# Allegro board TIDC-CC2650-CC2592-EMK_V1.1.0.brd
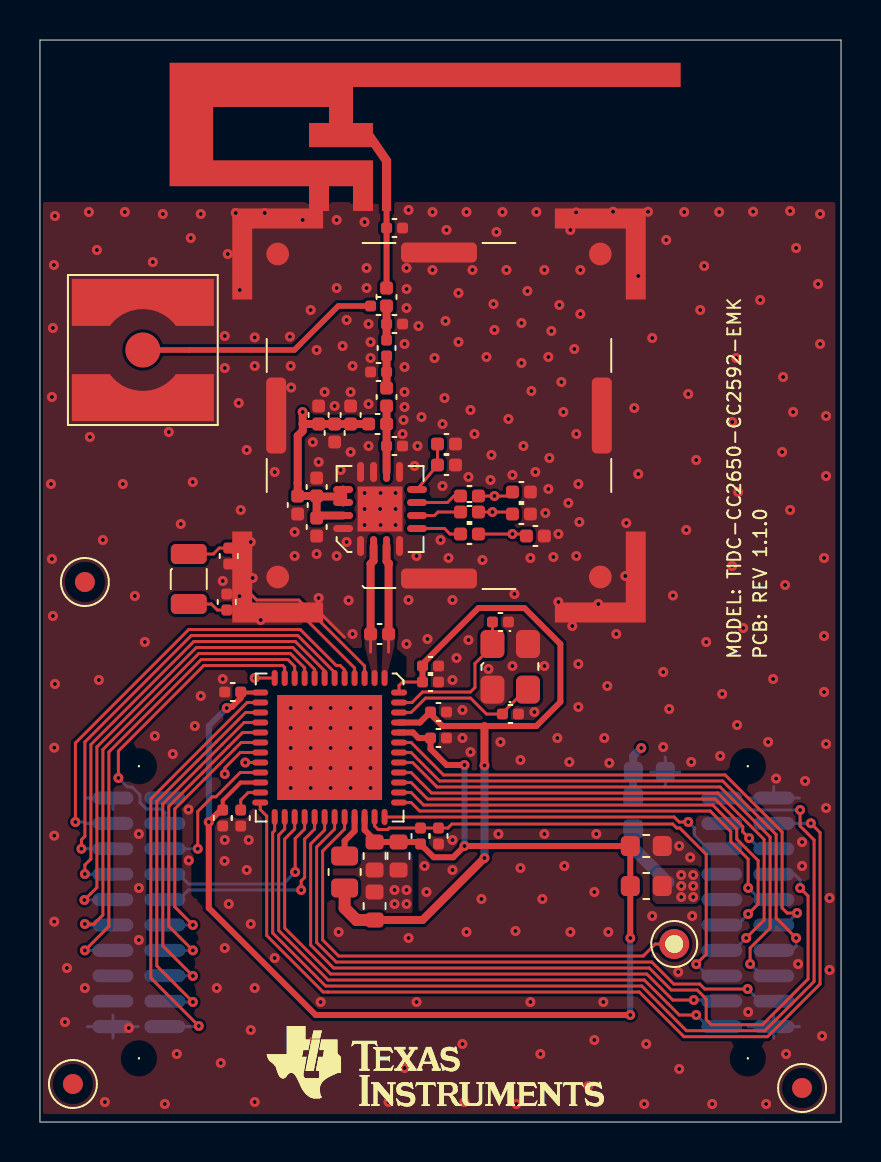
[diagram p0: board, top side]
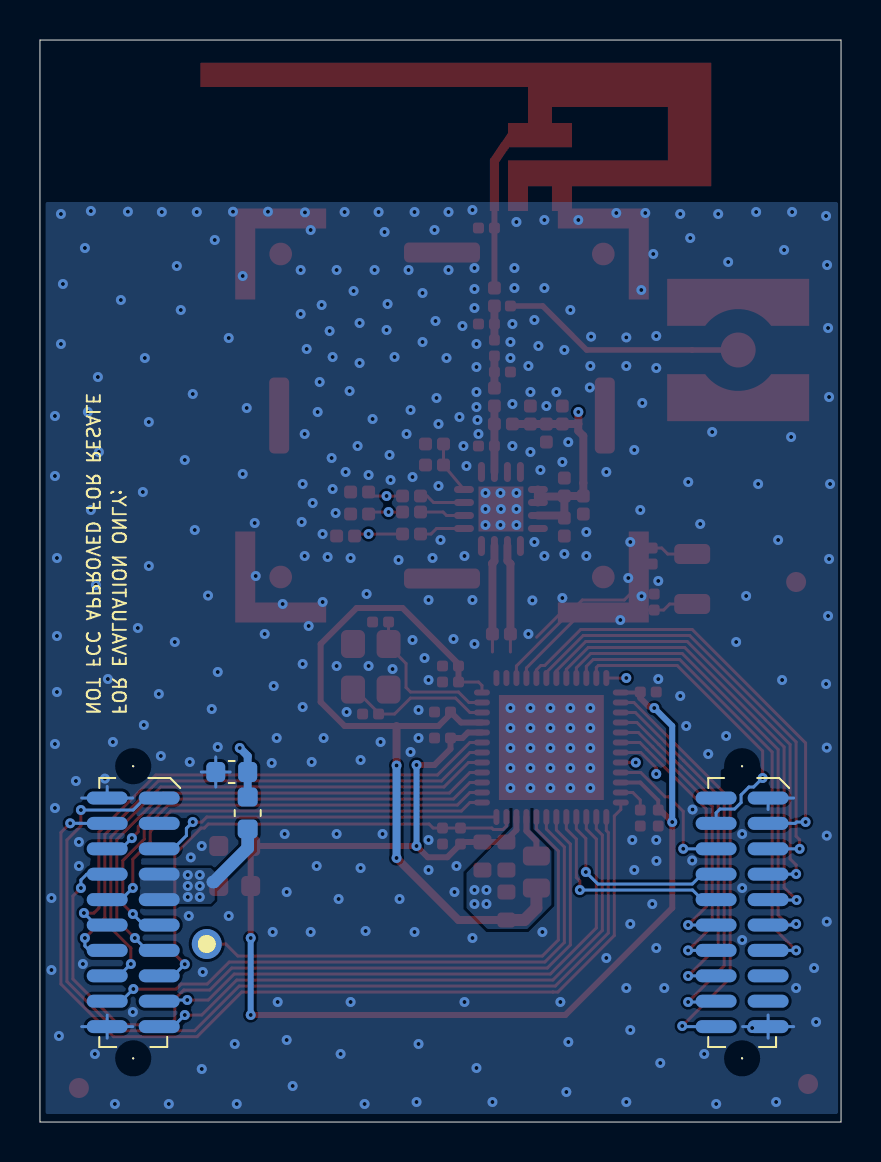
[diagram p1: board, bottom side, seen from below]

Outline 40.1 x 54.1 mm; copper layers: TOP, L2, L3, BOTTOM. Coordinates in mm from the lower left corner of the outline.
Outline path: 0,54.1 0,0 40.1,0 40.1,54.1 0,54.1

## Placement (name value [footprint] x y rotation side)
A1  2.4GHz  [ANTENNA_DN007N]  17.35 45.8 0 top
C1  10uF  [CAPC1608X90N]  16.75 10.1 90 top
C2  DNM  [CAPC1608X90N#2]  29.55 13.8 0 top
C3  100nF  [CAPC1005X60N#2]  10.05 21.5 180 top
C4  100nF  [CAPC1005X60N#2]  9.15 15.6 270 top
C5  100nF  [CAPC1005X60N#2]  19.55 19.2 0 top
C6  10uF  [CAPC1608X90N]  16.75 14 270 top
C7  100nF  [CAPC1608X90N]  17.95 14 270 top
C8  100nF  [CAPC1005X60N#2]  19.15 22 0 top
C9  100nF  [CAPC1005X60N#2]  19.55 20.5 0 top
C10  DNM_0402  [CAPC1005X60N#2]  19.15 22.8 0 top
C11  2.2uF  [CAPC1608X90N#2]  29.7 17.5 0 bottom
C12  2.2pF  [CAPC1005X60N#2]  17.35 33.8 0 top
C13  2.2pF  [CAPC1005X60N#2]  17.35 37.5 180 top
C14  1pF  [CAPC1005X60N#2]  17.35 39.9 0 top
C15  DNM_0402  [CAPC1005X60N#2]  17.35 44.7 0 top
C16  1nF  [CAPC1005X60N]  13.85 31.3 90 top
C17  12pF  [CAPC1005X60N#2]  9.45 28.7 270 top
C18  12pF  [CAPC1005X60N#2]  9.35 25.6 90 top
C19  12pF  [CAPC1005X60N]  13.85 30.2 270 top
C20  100nF  [CAPC1005X60N#2]  19.95 14.7 270 top
C21  1uF  [CAPC1005X60N]  13.95 34.9 90 top
C22  DNM_0402  [CAPC1005X60N#2]  23.15 20.4 0 top
C23  DNM_0402  [CAPC1005X60N#2]  22.65 25 0 top
C24  DNM_0402  [CAPC1005X60N#2]  16.55 40.8 0 top
C25  12pF  [CAPC1005X60N]  15.55 34.9 90 top
C26  1nF  [CAPC1005X60N]  14.75 34.9 270 top
C27  18pF  [CAPC1005X60N]  17.35 40.8 90 top
C28  1uF  [CAPC1005X60N#2]  10.05 15.6 270 top
C29  DNM_0402  [CAPC1005X60N]  19.9 33.9 0 top
C32  DNM_0402  [CAPC1005X60N]  12.9 31.3 270 top
C36  1.5pF  [CAPC1005X60N]  24.55 31.5 180 top
C37  1.5pF  [CAPC1005X60N]  24.55 30.4 180 top
C38  1.5pF  [CAPC1005X60N]  25.25 29.3 180 top
DIO22  TP_0.9mm_PTH  [TP150_90H]  31.75 8.9 0 top
FIDU1  FIDU_1MM  [FID100X115B]  1.65 1.9 0 top
FIDU2  FIDU_1MM  [FID100X115B]  38.15 1.7 0 top
FIDU3  FIDU_1MM  [FID100X115B]  2.25 27 0 top
FL1  BLM18HE152SN1  [FIL_BLM18HE152SN1DN]  29.55 11.8 0 top
FL2  BLM18HE152SN1  [FIL_BLM18HE152SN1DN]  29.7 16.25 270 bottom
J1  142-0711-201  [CINCH_1420711201_A2N]  5.15 38.6 90 top
L1  10uH  [INDC2012X150N]  15.25 13.3 270 top
L2  4.7nH  [INDC1005X60N]  16.45 34.9 0 top
L3  TBD  [INDC1005X60N]  17.45 24.4 180 top
L4  1nH  [INDC1005X60N]  17.35 35.8 90 top
L13  2nH  [INDC1005X60N#2]  17.35 38.3 90 top
NOREF  -  []  0 54.1 0 top
NOREF#2  -  []  40.1 0 90 top
P1  SFM-110-02-S-D-A-K-TR  [SAMTEC_SFM11002AN]  3.65 16.2 0 bottom
P2  SFM-110-02-S-D-A-K-TR  [SAMTEC_SFM11002AN]  34.13 16.2 0 bottom
R1  100k  [RESC1005X40N#2]  19.05 14.7 270 top
R2  3.9k  [RESC1005X40N]  20.8 32.85 180 top
R13  10k  [RESC1005X40N]  21.05 29.4 0 top
R14  10k  [RESC1005X40N]  21.05 30.5 0 top
R15  10k  [RESC1005X40N]  21.05 31.3 0 top
SC2  BMIS-202-F  [MECH_BMIS202FN]  11.9 27.25 0 top
U1  CC2650F128RGZ  [QFNFC50P700X700X80-49CN]  17.25 22.2 180 top
U2  CC2592  [QFNFC65P400X400X100-17AN]  16.05 28.8 0 top
UNK#REFDES  -  []  12.35 4.8 0 top
Y1  32.768kHz  [XTAL_FC-135N]  7.45 28.4 270 top
Y2  24MHz  [OSCCC250X320X60-4N]  22.65 23.9 270 top

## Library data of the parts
A1 = ANTENNA_DN007
C1 C2 C6 C7 C11 = CAPACITOR: alternate symbols: (CAPC1608X90L,CAPC1608X90M)
C3-C5 C8-C10 C12-C15 C17 C18 C20 C22-C24 C28 = CAPACITOR: alternate symbols: (CAPC1005X60L,CAPC1005X60M)
C16 C19 C21 C25-C27 C29 C32 C36-C38 = CAPACITOR: User Part Number: #PN; alternate symbols: (CAPC1005X60L,CAPC1005X60M)
DIO22 = TEST_POINT
FIDU1-FIDU3 = FIDMARK
FL1 FL2 = FILTER_2PIN: alternate symbols: (FIL_BLM18HE152SN1DL,FIL_BLM18HE152SN1DM)
J1 = CONN_COAX_1_J_2MH_V1: User Part Number: #PN; alternate symbols: (CINCH_1420711201_A2L,CINCH_1420711201_A2M)
L1 = INDUCTOR: alternate symbols: (INDC2012X150L,INDC2012X150M)
L2 L4 L13 = INDUCTOR: alternate symbols: (INDC1005X60L,INDC1005X60M)
L3 = INDUCTOR: alternate symbols: (INDC1005X60M,INDC1005X60L)
P1 P2 = CONN_HEADER_2X10_P_S: alternate symbols: (SAMTEC_SFM11002AL,SAMTEC_SFM11002AM)
R1 R2 R13-R15 = RESISTOR: alternate symbols: (RESC1005X40L,RESC1005X40M)
SC2 = SHIELD_COVER_BMIS-202: User Part Number: #PN
U1 = IC_RF_CC26XX_QFN48_V2: alternate symbols: (QFNFC50P700X700X80-49CL,QFNFC50P700X700X80-49CM)
U2 = IC_RF_CC2592_QFN16_V1: alternate symbols: (QFNFC65P400X400X100-17AL,QFNFC65P400X400X100-17AM)
Y1 = CRYSTAL: alternate symbols: (XTAL_FC-135L,XTAL_FC-135M)
Y2 = XTAL_4PIN_S: alternate symbols: (OSCCC250X320X60-4L,OSCCC250X320X60-4M)

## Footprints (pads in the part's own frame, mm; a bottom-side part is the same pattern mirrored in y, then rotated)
ANTENNA_DN007N
  rect 0.46x0.5 smd: 1(0,0)
  rect 1x0.5 smd: 2(-1.18,0) 3(-3.38,0)
CAPC1005X60N
  custom 0.16x0.16 smd: 1(0,0) 2(0.9,0)
CAPC1005X60N#2
  custom 0.135x0.135 smd: 1(0,0) 2(0.8,0)
CAPC1608X90N
  custom 0.188x0.188 smd: 1(0,0) 2(1.4,0)
CAPC1608X90N#2
  custom 0.237x0.237 smd: 1(0,0) 2(1.6,0)
CINCH_1420711201_A2N
  round 1.75 smd: 1(0,0)
  custom 0.588x0.588 smd: M1(-2.38,0) M2(2.38,0)
FID100X115B
  round 1 smd: 1(0,0)
FIL_BLM18HE152SN1DN
  custom 0.237x0.237 smd: 1(0,0) 2(1.6,0)
INDC1005X60N
  custom 0.16x0.16 smd: 1(0,0) 2(0.9,0)
INDC1005X60N#2
  custom 0.135x0.135 smd: 1(0,0) 2(0.8,0)
INDC2012X150N
  custom 0.237x0.237 smd: 1(0,0) 2(1.6,0)
MECH_BMIS202FN
  custom 1.137x1.137 smd: 1(0,0) 3(16.15,0) 5(16.15,16.15) 7(0,16.15)
  custom 0.25x0.25 smd: 2(8.075,-0.075) 4(16.225,8.075) 6(8.075,16.225) 8(-0.075,8.075)
OSCCC250X320X60-4N
  custom 0.3x0.3 smd: 1(0,0) 2(2.28,0) 3(2.28,1.78) 4(0,1.78)
QFNFC50P700X700X80-49CN
  oval 0.3x0.8 smd: 1(0,0) 2(0.5,0) 3(1,0) 4(1.5,0) 5(2,0) 6(2.5,0) 7(3,0) 8(3.5,0) 9(4,0) 10(4.5,0) 11(5,0) 12(5.5,0) 25(5.5,6.95) 26(5,6.95) 27(4.5,6.95) 28(4,6.95) 29(3.5,6.95) 30(3,6.95) 31(2.5,6.95) 32(2,6.95) 33(1.5,6.95) 34(1,6.95) 35(0.5,6.95) 36(0,6.95)
  oval 0.8x0.3 smd: 13(6.225,0.725) 14(6.225,1.225) 15(6.225,1.725) 16(6.225,2.225) 17(6.225,2.725) 18(6.225,3.225) 19(6.225,3.725) 20(6.225,4.225) 21(6.225,4.725) 22(6.225,5.225) 23(6.225,5.725) 24(6.225,6.225) 37(-0.725,6.225) 38(-0.725,5.725) 39(-0.725,5.225) 40(-0.725,4.725) 41(-0.725,4.225) 42(-0.725,3.725) 43(-0.725,3.225) 44(-0.725,2.725) 45(-0.725,2.225) 46(-0.725,1.725) 47(-0.725,1.225) 48(-0.725,0.725)
  rect 5.25x5.25 smd: 49(2.75,3.475)
QFNFC65P400X400X100-17AN
  oval 0.35x1 smd: 1(0,0) 2(0.65,0) 3(1.3,0) 4(1.95,0) 9(1.95,3.7) 10(1.3,3.7) 11(0.65,3.7) 12(0,3.7)
  oval 1x0.35 smd: 5(2.825,0.875) 6(2.825,1.525) 7(2.825,2.175) 8(2.825,2.825) 13(-0.875,2.825) 14(-0.875,2.175) 15(-0.875,1.525) 16(-0.875,0.875)
  rect 2.25x2.25 smd: 17(0.975,1.85)
RESC1005X40N
  custom 0.16x0.16 smd: 1(0,0) 2(0.9,0)
RESC1005X40N#2
  custom 0.135x0.135 smd: 1(0,0) 2(0.8,0)
SAMTEC_SFM11002AN
  round 0.1 hole 1.5 unplated: (1.302,-1.588) (1.302,13.017)
  oval 2.05x0.65 smd: 1(0,0) 2(2.604,0) 3(0,1.27) 4(2.604,1.27) 5(0,2.54) 6(2.604,2.54) 7(0,3.81) 8(2.604,3.81) 9(0,5.08) 10(2.604,5.08) 11(0,6.35) 12(2.604,6.35) 13(0,7.62) 14(2.604,7.62) 15(0,8.89) 16(2.604,8.89) 17(0,10.16) 18(2.604,10.16) 19(0,11.43) 20(2.604,11.43)
TP150_90H
  round 1.5 hole 0.9: 1(0,0)
XTAL_FC-135N
  custom 0.25x0.25 smd: 1(0,0) 2(2.5,0)

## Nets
GND: A1.2(GND_2) A1.3(GND_3) C1.2 C2.2 C3.2 C4.2 C5.2 C6.2 C7.2 C8.2 C9.2 C10.2 C11.2 C12.2 C13.2 C14.2 C15.2 C16.2 C17.2 C18.2 C19.2 C20.2 C21.2 C22.2 C23.2 C25.2 C26.2 C28.2 C29.2 C32.2 C36.1 C37.1 C38.1 J1.M1 J1.M2 P1.1 P1.19 P2.2 P2.20 R2.1 SC2.1(GND#1) SC2.2(GND#2) SC2.3(GND#3) SC2.4(GND#4) SC2.5(GND#5) SC2.6(GND#6) SC2.7(GND#7) SC2.8(GND#8) U1.49(VSS) U2.1(GND#1) U2.4(GND#4) U2.9(GND#9) U2.11(GND#11) U2.12(GND#12) U2.16(GND#16) U2.17(EGP/GND) Y2.2 Y2.4
VDD_CC2592: C11.1 C16.1 C19.1 C21.1 C25.1 C26.1 C32.1 FL2.1 L2.1 U2.13(VDD_LNA) U2.14(VDD_BIAS) U2.15(VDD_PA)
VDD_EB: FL1.2 FL2.2 P2.7 P2.9
VDDR: C1.1 C8.1 C9.1 C10.1 L1.2 U1.45(VDDR#45) U1.48(VDDR#48)
VDDS: C2.1 C3.1 C4.1 C5.1 C6.1 C7.1 FL1.1 R1.2 U1.13(VDDS2) U1.22(VDDS3) U1.34(VDDS_DCDC) U1.44(VDDS)
DCDC_SW: L1.1 U1.33(DCDC_SW)
DIO_0: P1.3 U1.5(DIO_0)
DIO_1: P1.5 U1.6(DIO_1)
DIO_2: P1.7 U1.7(DIO_2)
DIO_3: P1.9 U1.8(DIO_3)
DIO_4: P1.11 U1.9(DIO_4)
DIO_5: P1.13 U1.10(DIO_5)
DIO_6: P1.4 U1.11(DIO_6)
DIO_7: C38.2 R13.2 U1.12(DIO_7)
DIO_8: P1.20 U1.14(DIO_8)
DIO_9: P1.18 U1.15(DIO_9)
DIO_10: P1.16 U1.16(DIO_10)
DIO_11: P1.14 U1.17(DIO_11)
DIO_12: P1.12 U1.18(DIO_12)
DIO_13: C37.2 R14.2 U1.19(DIO_13)
DIO_14: C36.2 R15.2 U1.20(DIO_14)
DIO_15: P1.6 U1.21(DIO_15)
DIO_16 / JTAG TDO: P2.19 U1.26(DIO_16)
DIO_17 / JTAG TDI: P2.17 U1.27(DIO_17)
DIO_18: P1.8 U1.28(DIO_18)
DIO_19: P1.10 U1.29(DIO_19)
DIO_20: P2.8 U1.30(DIO_20)
DIO_21: P2.18 U1.31(DIO_21)
DIO_22: DIO22.1 U1.32(DIO_22)
DIO_23: P2.5 U1.36(DIO_23)
DIO_24: P2.10 U1.37(DIO_24)
DIO_25: P2.11 U1.38(DIO_25)
DIO_26: P2.6 U1.39(DIO_26)
DIO_27: P2.13 U1.40(DIO_27)
DIO_28: P2.16 U1.41(DIO_28)
DIO_29: P2.14 U1.42(DIO_29)
DIO_30: P2.12 U1.43(DIO_30)
JTAG_TCK: P2.1 U1.25(JTAG_TCKC)
JTAG_TMS: P2.4 U1.24(JTAG_TMSC)
NRESET: C20.1 P2.15 R1.1 U1.35(RESET_N)
N310466: C23.1 U1.47(X24M_P) Y2.1
N310868: C22.1 U1.46(X24M_N) Y2.3
N314494: L3.1 U1.1(RF_P) U2.3(RF_P)
N314505: L3.2 U1.2(RF_N) U2.2(RF_N)
N314786: C12.1 L2.2 L4.1 U2.10(ANT)
N315193: C13.1 L4.2 L13.1
N316022: A1.1(FEED_1) C15.1 C27.2
N316040: C24.1 J1.1
N316649: C28.1 U1.23(DCOUPL)
N316919: C17.1 U1.3(X32K_Q1) Y1.1
N316932: C18.1 U1.4(X32K_Q2) Y1.2
N334495: C14.1 C24.2 C27.1 L13.2
N435366: R15.1 U2.7(HGM)
N435370: R14.1 U2.6(LNA_EN)
N435374: R13.1 U2.5(PA_EN)
N443687: C29.1 R2.2 U2.8(BIAS)

Pads without a net: FIDU1 1; FIDU2 1; FIDU3 1; P1 2 15 17; P2 3

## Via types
v1: diameter 0.5, hole 0.2, TOP to BOTTOM, 401 vias

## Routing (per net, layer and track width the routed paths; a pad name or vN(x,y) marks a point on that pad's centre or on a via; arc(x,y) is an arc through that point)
GND: length 17.9
  TOP w0.15: 15.24,24.24 13.95,25.53 v1(13.95,26.2)
  BOTTOM w0.15: C11.2 32.03,17.5 ; C11.2 31.3,18.25 ; C11.2 31.3,16.75 ; C11.2 30.57,17.5 ; P2.2 38.01,16.2 ; P2.2 35.46,16.2 ; P2.2 36.73,16.78 ; 2.37,16.2 P1.1 3.65,15.62 ; P2.20 38.01,4.77 ; P2.20 36.73,4.19 ; P2.20 36.73,5.35 ; P2.20 35.46,4.77 ; 3.65,4.19 P1.19 ; P1.19 3.65,5.35 ; P1.19 2.37,4.77 ; P1.19 4.93,4.77
  vias: v1(0.55,31.9) v1(0.7,42.85) v1(0.65,39.7) v1(0.6,36.25) v1(0.6,28.15) v1(0.65,25.3) v1(0.75,45.3) v1(0.75,21.9) v1(0.72,18.72) v1(0.72,14.32) v1(0.72,10.02) v1(1.25,5) v1(1.35,7.7) v1(2.25,6.7) v1(2.45,45.5) v1(2.5,34.25) v1(2.85,43.6) v1(2.95,22.1) v1(3.15,29.1) v1(3.25,1) v1(4.15,31.9) v1(4.25,45.5) v1(4.45,4.7) v1(4.75,26.3) v1(4.95,14.4) v1(4.95,11.7) v1(4.95,9.1) v1(5.25,24) v1(5.65,43) v1(5.75,19.3) v1(6.15,45.4) v1(6.25,0.9) v1(6.45,34.5) v1(6.65,18.4) v1(6.85,3.4) v1(7.05,29.9) v1(7.43,15.62) v1(7.45,13.08) v1(7.55,44.2) v1(7.65,32) v1(7.75,19.8) v1(8.05,45.4) v1(8.05,21.3) v1(8.85,6.7) v1(9.05,2.95) v1(9.15,27.05) v1(9.15,22.15) v1(9.25,39.3) v1(9.25,37.7) v1(9.25,14.1) v1(9.24,13.05) v1(9.25,8.7) v1(9.4,43.4) v1(9.45,10.9) v1(9.8,45.45) v1(10,41.6) v1(9.95,35.95) v1(9.99,26.29) v1(10.05,30.6) v1(10.35,33.6) v1(10.35,12.6) v1(10.45,14.1) v1(10.55,29) v1(10.55,9.9) v1(10.55,4.6) v1(10.65,27.2) v1(10.75,39.23) v1(10.75,37.8) v1(10.75,6.7) v1(10.75,1) v1(11.05,25.1) v1(11.25,45.45) v1(11.75,32.5) v1(11.75,8.2) v1(12.51,39.27) v1(12.55,37.8) v1(12.58,36.72) v1(12.55,20.7) v1(12.55,19.7) v1(12.55,18.7) v1(12.55,17.7) v1(12.55,16.7) v1(12.75,29.5) v1(12.75,28.3) v1(13.15,45.1) v1(13.55,40.6) v1(13.55,20.7) v1(13.55,19.7) v1(13.55,18.7) v1(13.55,17.7) v1(13.55,16.7) v1(13.66,33.99) v1(13.65,4) v1(13.75,1.5) v1(13.85,38.6) v1(13.85,28.4) v1(13.95,33) v1(14.05,6) v1(14.25,36.5) v1(14.55,20.7) v1(14.55,19.7) v1(14.55,18.7) v1(14.55,17.7) v1(14.55,16.7) v1(14.75,35.8) v1(14.85,45.1) v1(14.85,41.7) v1(14.85,28.3) v1(14.95,9.5) v1(15.05,32.6) v1(15.15,38.8) v1(15.35,40.1) v1(15.35,29) v1(15.45,26.08) v1(15.55,36.5) v1(15.55,33.5) v1(15.55,20.7) v1(15.55,19.7) v1(15.55,18.7) v1(15.55,17.7) v1(15.55,16.7) v1(15.65,37.8) v1(15.65,24.4) v1(16.25,45) v1(16.25,31.45) v1(16.25,30.65) v1(16.25,29.85) v1(16.35,42.7) v1(16.35,41.7) v1(16.45,39.9) v1(16.45,35.9) v1(16.45,33.8) v1(16.55,39) v1(16.55,38.2) v1(16.55,20.7) v1(16.55,19.7) v1(16.55,18.7) v1(16.55,17.7) v1(16.55,16.7) v1(17.05,31.45) v1(17.03,30.65) v1(17.05,29.85) v1(17.45,1) v1(17.75,11.6) v1(17.75,10.9) v1(17.8,31.45) v1(17.8,30.65) v1(17.8,29.85) v1(18.2,35.1) v1(18.15,34.4) v1(18.25,38.9) v1(18.25,37.75) v1(18.25,36.5) v1(18.25,35.75) v1(18.25,2.7) v1(18.35,42.7) v1(18.35,41.65) v1(18.35,40.7) v1(18.35,23.9) v1(18.35,11.6) v1(18.35,10.9) v1(18.45,45.6) v1(18.45,26.1) v1(18.45,9.2) v1(18.75,32.8) v1(18.9,33.8) v1(18.85,28.3) v1(18.85,6) v1(18.95,39.8) v1(19.1,35.25) v1(19.25,12.8) v1(19.35,11.5) v1(19.4,24.15) v1(19.65,45.5) v1(19.65,42.6) v1(19.75,38.2) v1(20.05,29.1) v1(20.15,34.9) v1(20.15,31.8) v1(20.25,36.2) v1(20.35,44.6) v1(20.3,40.05) v1(20.45,28.2) v1(20.65,26.1) v1(20.65,22.1) v1(20.65,14.1) v1(20.65,12.6) v1(20.85,23.2) v1(20.95,41.45) v1(20.95,39) v1(21.15,20.6) v1(21.15,19.2) v1(21.15,3.9) v1(21.25,1) v1(21.35,45.5) v1(21.35,9.5) v1(21.45,32.25) v1(21.45,24.1) v1(21.55,35.6) v1(21.55,18.5) v1(21.65,42.6) v1(21.75,34.4) v1(22.1,11.15) v1(22.15,28.1) v1(22.35,38.25) v1(22.45,22.65) v1(22.6,33.35) v1(22.55,32.1) v1(22.7,40.9) v1(22.75,39.6) v1(22.85,44.5) v1(22.95,14.4) v1(23.05,19) v1(23.15,45.5) v1(23.35,42.6) v1(23.45,35.15) v1(23.65,32.35) v1(23.65,22.8) v1(23.75,26.4) v1(23.8,9.55) v1(23.85,0.9) v1(24.1,39.95) v1(24.1,37.95) v1(24.05,18.1) v1(24.05,12.7) v1(24.2,33.8) v1(24.4,41.55) v1(24.6,36.55) v1(24.55,28.2) v1(24.55,6) v1(24.75,20.5) v1(24.85,45.5) v1(24.8,32.5) v1(25.05,3.4) v1(25.15,11.15) v1(25.25,42.6) v1(25.25,22.8) v1(25.25,14.4) v1(25.3,30.45) v1(25.45,38.25) v1(25.5,33.2) v1(25.45,31.65) v1(25.6,39.55) v1(25.7,28.25) v1(25.9,19.2) v1(26,40.85) v1(25.95,29.4) v1(25.95,26) v1(26.1,37) v1(26.2,35.5) v1(26.25,12.8) v1(26.45,30.95) v1(26.5,18) v1(26.55,44.6) v1(26.55,9.5) v1(26.65,24.8) v1(26.75,38.65) v1(26.84,45.48) v1(26.85,34.4) v1(26.85,28.3) v1(26.95,31.9) v1(27,30) v1(26.95,22.9) v1(26.95,20.75) v1(27.05,42.6) v1(27.05,40.4) v1(27.45,1.8) v1(27.75,11.5) v1(27.75,4.1) v1(27.85,14.4) v1(27.95,25.9) v1(28.25,19.2) v1(28.2,6) v1(28.4,21.8) v1(28.5,17.95) v1(28.45,9.5) v1(28.69,45.51) v1(28.85,24.4) v1(29.35,29.95) v1(29.3,27.3) v1(29.75,35.7) v1(29.95,42.3) v1(29.95,32.4) v1(30.25,0.9) v1(30.35,3.9) v1(30.44,45.51) v1(30.65,39.2) v1(30.65,10.3) v1(31.2,22.5) v1(31.2,18.75) v1(31.35,44.1) v1(31.5,20.65) v1(31.69,26.32) v1(31.95,7.5) v1(32,2.65) v1(32,13.8) v1(32.25,45.5) v1(32.35,29.6) v1(32.45,36.4) v1(32.6,18) v1(32.55,13.23) v1(32.65,10.3) v1(32.85,33.1) v1(33.05,40.6) v1(33.25,42.8) v1(33.35,24) v1(33.65,0.9) v1(34,45.5) v1(34.05,18.3) v1(34.15,21.4) v1(34.65,35) v1(34.65,27.8) v1(34.85,38.2) v1(34.9,19.85) v1(34.95,31.5) v1(35.2,24.7) v1(35.45,5.5) v1(35.7,45.52) v1(36.05,41.1) v1(36.35,0.9) v1(36.45,19) v1(36.7,22.15) v1(36.85,17.17) v1(37.15,33.5) v1(37.2,37.25) v1(37.3,26.85) v1(37.35,3.4) v1(37.55,45.55) v1(37.55,30.6) v1(37.7,35.5) v1(37.85,43.7) v1(37.95,7.9) v1(38.15,14) v1(38.15,12.8) v1(38.3,17.05) v1(38.95,41.9) v1(39.05,45.4) v1(39.05,38.9) v1(39.15,4.3) v1(39.25,28.2) v1(39.25,24.3) v1(39.25,21.5) v1(39.35,35.3) v1(39.35,32.3) v1(39.35,18.9) v1(39.35,15.7) v1(39.53,11.2) v1(39.53,7.6)
VDD_CC2592: length 48.5
  TOP w0.15: 13.96,30.33 13.85,30.43 C19.1 ; C16.1 13.88,31.27
  TOP w0.4: U2.15 13.96,30.33 ; 13.16,34.9 C21.1 C26.1 C25.1 L2.1 ; 13.16,34.9 13.15,34.91 v1(13.15,35.5) ; 13.16,34.9 13.16,34.56 12.9,34.3 12.9,31.95 12.9,31.95 C32.1 C16.1 13.85,30.43 ; 13.88,31.27 15.18,31.27 ; 15.18,31.27 U2.13 ; 15.18,31.27 15.18,30.98
  L3 w0.4: v1(13.15,35.5) 13.15,36.55 13.7,37.1 22.75,37.1 26.95,32.9 27.85,32.9 30.1,30.65 v1(30.1,18.7)
  BOTTOM w0.4: v1(30.1,18.7) 29.7,18.3 C11.1 FL2.1
VDD_EB: length 3.4
  BOTTOM w0.63: FL2.2 29.7,13.7 31.4,12 31.45,12
  vias: v1(32.1,12.35) v1(32.1,11.8) v1(32.1,11.25) v1(32.7,12.35) v1(32.7,11.8) v1(32.7,11.25)
VDDR: length 39.5
  TOP w0.15: U1.48 17.98,21.83 18.15,22 C8.1
  TOP w0.3: U1.45 19.02,19.98 19.55,20.5 C9.1 19.55,20.4 20.15,19.8 24.85,19.8 26.05,21 26.05,23.9 24.25,25.7 21.95,25.7 19.15,22.9 C10.1 C8.1
  TOP w0.4: C1.1 19.15,10.1 v1(22.25,13.2) ; v1(22.25,17.83) 22.25,19.8
  TOP w0.6: L1.2 15.25,10.7 15.85,10.1 C1.1
  BOTTOM w0.4: v1(22.25,13.2) v1(22.25,17.83)
VDDS: length 71.1
  TOP w0.2: C3.1 10.08,21.48 U1.13 ; U1.22 10.05,16.98 9.15,16.08 C4.1
  TOP w0.3: U1.34 16.25,14.6 16.75,14.1 C6.1 C7.1 18.95,14 R1.2 19.05,13.89 19.71,13.24 20.69,13.24 v1(21.25,13.8) C2.1 FL1.1 v1(29.55,9.2) ; v1(21.25,17.85) 20.35,17.85 19.55,18.65 C5.1 18.95,19.2 18.68,19.48 U1.44 ; v1(29.55,5.35) 13.8,5.35 8.45,10.7 v1(8.45,15) 9.05,15.6 C4.1 ; C3.1 10.05,21.2 9.62,20.77 9.42,20.77 v1(9.35,20.7)
  BOTTOM w0.3: v1(8.45,15) 8.45,19.8 v1(9.35,20.7) ; v1(21.25,13.8) v1(21.25,17.85) ; v1(29.55,9.2) v1(29.55,5.35)
DCDC_SW: length 2.2
  TOP w0.3: U1.33 15.75,14.55 15.25,14.05 L1.1
DIO_0: length 22.9
  TOP w0.15: U1.5 15.25,22.6 15.03,22.83 14.83,22.83 13.03,24.62 7.45,24.62 1.78,18.95 v1(1.78,15)
  BOTTOM w0.15: P1.3 2.3,14.93 2.23,15 v1(1.78,15)
DIO_1: length 22.7
  TOP w0.15: U1.6 14.75,22.48 12.91,24.33 7.58,24.33 2.25,19 2.25,14.29 2.08,14.11 v1(2.08,13.66)
  BOTTOM w0.15: v1(2.08,13.66) P1.5
DIO_2: length 22.8
  TOP w0.15: U1.7 14.25,22.56 12.78,24.03 7.7,24.03 2.55,18.88 2.55,13.15 2.25,12.85 v1(2.25,12.4)
  BOTTOM w0.15: v1(2.25,12.4) 2.45,12.4 2.46,12.39 P1.7
DIO_3: length 23.2
  TOP w0.15: U1.8 13.75,22.63 12.66,23.73 7.83,23.73 2.85,18.75 2.85,11.72 2.55,11.42 v1(2.23,11.1)
  BOTTOM w0.15: P1.9 3.63,11.1 v1(2.23,11.1)
DIO_4: length 23.7
  TOP w0.15: v1(2.25,9.9) 2.7,9.9 3.15,10.35 3.15,18.62 7.95,23.42 12.53,23.42 13.25,22.71 U1.9
  BOTTOM w0.15: P1.11 2.5,9.85 2.45,9.9 v1(2.25,9.9)
DIO_5: length 23.8
  TOP w0.15: v1(2.25,8.58) 3.45,9.78 3.45,18.5 8.08,23.12 12.41,23.12 12.75,22.78 U1.10
  BOTTOM w0.15: P1.13 v1(2.25,8.58)
DIO_6: length 15.8
  TOP w0.15: U1.11 12.25,22.73 12.15,22.83 8.2,22.83 3.93,18.55 v1(3.93,17.2)
  BOTTOM w0.15: P1.4 6.25,15.46 6.06,15.65 5.33,15.65 5,15.97 5,16.36 4.61,16.75 4.38,16.75 v1(3.93,17.2)
DIO_7: length 20.9
  TOP w0.15: C38.2 24.25,29.4 v1(23.65,29.4) R13.2 ; U1.12 v1(10.75,22.2)
  L3 w0.15: v1(10.75,22.2) 10.75,22.7 13.05,25 21.45,25 23.55,27.1 23.55,28.85 23.65,28.95 v1(23.65,29.4)
DIO_8: length 21.5
  TOP w0.15: v1(7.95,4.8) 5.55,7.2 5.55,16.16 10.37,20.98 U1.14
  BOTTOM w0.15: v1(7.95,4.8) 7.92,4.77 P1.20
DIO_9: length 19.2
  TOP w0.15: U1.15 10.29,20.48 8.82,19 8.82,19 7.88,18.06 5.85,16.03 5.85,7.81 v1(7.66,6)
  BOTTOM w0.15: P1.18 6.29,6 v1(7.66,6)
DIO_10: length 17.2
  TOP w0.15: U1.16 10.22,19.98 9.12,18.88 9.12,18.88 8,17.76 8,17.76 6.15,15.91 6.15,8.81 v1(7.66,7.3)
  BOTTOM w0.15: v1(7.66,7.3) 7.49,7.3 7.48,7.31 P1.16
DIO_11: length 15.2
  TOP w0.15: U1.17 10.14,19.48 9.42,18.75 8.13,17.46 8.13,17.46 6.45,15.78 6.45,9.79 v1(7.66,8.58)
  BOTTOM w0.15: v1(7.66,8.58) P1.14
DIO_12: length 13.2
  TOP w0.15: v1(7.66,9.85) 6.75,10.76 6.75,15.66 8.25,17.16 10.07,18.98 U1.18
  BOTTOM w0.15: v1(7.66,9.85) P1.12
DIO_13: length 27.9
  TOP w0.15: R14.2 v1(22.65,30.5) 23.55,30.5 C37.2 ; v1(9.25,17.4) 9.25,17.7 10.03,18.48 U1.19
  L3 w0.15: v1(9.25,17.4) 9.25,19.45 9.97,20.17 9.98,22.78 9.98,22.78 9.98,23.06 12.52,25.61 21.21,25.61 22.65,27.05 v1(22.65,30.5)
DIO_14: length 26.5
  TOP w0.15: C36.2 23.45,31.3 v1(22.75,31.3) R15.2 ; U1.20 v1(10.28,17.98)
  L3 w0.15: v1(10.28,17.98) 10.28,22.65 10.28,22.66 10.28,22.83 12.75,25.3 21.33,25.3 23.15,27.12 23.15,31.15 23,31.3 v1(22.75,31.3)
DIO_15: length 7.4
  TOP w0.15: v1(7.9,13.66) 7.9,15.53 8.63,16.26 8.81,16.26 10.03,17.48 U1.21
  BOTTOM w0.15: P1.6 v1(7.9,13.66)
DIO_16 / JTAG TDO: length 30
  TOP w0.15: U1.26 12.25,14.65 11.95,14.35 11.95,9.57 14.42,7.1 30.25,7.1 32,5.35 v1(32.85,5.35)
  BOTTOM w0.15: v1(32.85,5.35) 33.43,4.77 P2.19
DIO_17 / JTAG TDI: length 29.2
  TOP w0.15: v1(32.73,6.1) 31.68,6.1 30.38,7.4 14.55,7.4 12.25,9.7 12.25,14.15 12.75,14.65 U1.27
  BOTTOM w0.15: v1(32.73,6.1) 33.37,6.1 33.43,6.04 P2.17
DIO_18: length 9.9
  TOP w0.15: U1.28 13.25,14.65 12.78,14.17 v1(12.78,12.5)
  BOTTOM w0.15: v1(12.78,12.5) 12.18,11.9 7.44,11.9 6.95,12.39 P1.8
DIO_19: length 10.9
  TOP w0.15: U1.29 13.75,14.65 13.25,14.15 13.25,12.23 13.08,12.05 v1(13.08,11.6)
  BOTTOM w0.15: v1(13.08,11.6) 7.43,11.6 6.95,11.12 P1.10
DIO_20: length 41.3
  TOP w0.15: U1.30 14.25,14.6 13.55,13.9 13.55,8.85 14.7,7.7 30.5,7.7 31.6,6.6 32.9,6.6 33.35,6.15 33.35,5.12 33.6,4.87 36.17,4.87 38.45,7.15 38.45,11.3 v1(38.05,11.7)
  BOTTOM w0.15: v1(38.05,11.7) 38.05,12.1 37.76,12.39 P2.8
DIO_21: length 30.7
  TOP w0.15: U1.31 14.75,14.65 13.85,13.75 13.85,8.98 14.83,8 30.62,8 31.72,6.9 33.03,6.9 33.28,6.65 v1(35.42,6.65)
  BOTTOM w0.15: v1(35.42,6.65) 36.03,6.04 P2.18
DIO_22: length 24.8
  TOP w0.15: DIO22.1 30.8,8.9 30.2,8.3 14.95,8.3 14.15,9.1 14.15,13.55 15.25,14.65 U1.32
DIO_23: length 17.7
  TOP w0.15: U1.36 31.75,15.25 32,15 v1(32.45,15)
  BOTTOM w0.15: v1(32.45,15) 32.77,14.68 32.77,14.32 33.43,13.66 P2.5
DIO_24: length 21.9
  TOP w0.15: v1(35.45,11.7) 35.45,13.15 34.58,14.02 34.58,14.52 33.55,15.55 19,15.55 18.58,15.98 U1.37
  BOTTOM w0.15: P2.10 36.03,11.12 v1(35.45,11.7)
DIO_25: length 24.1
  TOP w0.15: v1(35.45,10.4) 35.95,10.9 35.95,13.07 34.88,14.14 34.88,14.64 33.68,15.85 19.2,15.85 18.58,16.48 U1.38
  BOTTOM w0.15: v1(35.45,10.4) 34.9,9.85 P2.11
DIO_26: length 20.3
  TOP w0.15: U1.39 18.58,16.98 19.4,16.15 33.8,16.15 35.18,14.77 35.18,14.51 v1(35.5,14.19)
  BOTTOM w0.15: v1(35.5,14.19) 36.03,13.66 P2.6
DIO_27: length 26.4
  TOP w0.15: v1(35.35,9.2) 36.25,10.1 36.25,14.12 33.93,16.45 19.6,16.45 18.58,17.48 U1.40
  BOTTOM w0.15: v1(35.35,9.2) 34.73,8.58 P2.13
DIO_28: length 28.3
  TOP w0.15: U1.41 18.65,17.98 19.88,16.75 34.05,16.75 36.55,14.25 36.55,9.7 35.55,8.7 v1(35.55,7.9)
  BOTTOM w0.15: v1(35.55,7.9) 36.15,7.3 36.72,7.3 P2.16
DIO_29: length 27.8
  TOP w0.15: U1.42 18.58,18.48 20,17.05 34.17,17.05 36.85,14.38 36.85,10.2 v1(37.85,9.2)
  BOTTOM w0.15: P2.14 37.63,8.58 37.85,8.8 v1(37.85,9.2)
DIO_30: length 27.1
  TOP w0.15: v1(37.9,10.45) 37.4,10.45 37.15,10.7 37.15,14.5 34.3,17.35 20.2,17.35 18.58,18.98 U1.43
  BOTTOM w0.15: v1(37.9,10.45) 37.3,9.85 P2.12
JTAG_TCK: length 49
  TOP w0.15: v1(38.05,15.6) 38.05,14.8 38.75,14.1 38.75,7.03 36.29,4.57 32.36,4.57 30.12,6.8 14.3,6.8 11.65,9.45 11.65,14.47 11.75,14.57 U1.25
  BOTTOM w0.15: v1(38.05,15.6) 35.43,15.6 34.83,16.2 P2.1
JTAG_TMS: length 47.8
  TOP w0.15: U1.24 11.03,15.62 11.35,15.3 11.35,9.32 14.18,6.5 14.42,6.5 14.42,6.5 30,6.5 32.23,4.27 36.42,4.27 39.05,6.9 39.05,14.47 v1(38.59,14.94)
  BOTTOM w0.15: v1(38.59,14.94) 38.13,14.94 38.13,14.93 P2.4
NRESET: length 25.1
  TOP w0.15: U1.35 16.75,14.8 16.93,14.62 17.41,14.62 17.48,14.7 R1.1 C20.1 20.42,14.7 20.62,14.9 31.67,14.9 31.87,14.7 32.03,14.7 33.35,13.38 33.35,8.39 v1(32.85,7.89)
  BOTTOM w0.15: P2.15 33.43,7.31 v1(32.85,7.89)
N310466: length 7.7
  TOP w0.15: U1.47 18.62,20.98 19.15,21.5 21.55,21.5 21.78,21.73 21.78,22.92 22.65,23.8 Y2.1 C23.1
N310868: length 7.6
  TOP w0.15: 23.15,20.45 24.32,21.62 Y2.3 ; 23.15,20.45 C22.1 ; 23.15,20.45 23.1,20.4 22.35,20.4 21.55,21.2 19.3,21.2 18.58,20.48 U1.46
N314494: length 5.4
  TOP w0.15: L3.1 17.45,23.5
  TOP w0.4: L3.1 17.45,27.9 17.46,27.91 17.47,27.93 17.35,28.04 U2.3
N314505: length 5.4
  TOP w0.15: L3.2 16.55,23.5
  TOP w0.4: U2.2 16.7,28.06 16.55,27.91 16.55,27.91 L3.2
N314786: length 3.3
  TOP w0.4: U2.10 C12.1 L2.2 L4.1
N315193: length 1.6
  TOP w0.4: L13.1 C13.1 L4.2
N316022: length 4.1
  TOP w0.3: A1.1 C15.1 C27.2
N316040: length 12.3
  TOP w0.28: J1.1 7.45,38.6 7.46,38.6 12.73,38.6 14.93,40.8 C24.1
N316649: length 1.6
  TOP w0.15: U1.23 10.42,16.48 10.05,16.1 C28.1
N316919: length 12.7
  TOP w0.15: U1.3 16.25,22.8 12.95,26.1 10.85,26.1 9.95,27.01 9.95,28.2 9.45,28.7 C17.1 8.98,28.7 8.68,28.4 Y1.1
N316932: length 10.1
  TOP w0.15: Y1.2 8.58,25.9 8.88,25.6 C18.1 12.85,25.6 15.75,22.7 U1.4
N334495: length 1.7
  TOP w0.4: L13.2 C14.1 C27.1
N435366: length 2.3
  TOP w0.15: 18.88,30.98 20.4,30.98 20.72,31.3 R15.1
N435370: length 2.2
  TOP w0.15: R14.1 19.92,30.5 19.75,30.33 18.88,30.33
N435374: length 2.3
  TOP w0.15: 18.88,29.67 20.25,29.67 20.52,29.4 R13.1
N443687: length 2.6
  TOP w0.15: C29.1 R2.2 18.88,31.62

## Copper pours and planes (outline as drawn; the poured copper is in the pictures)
GND on TOP: 0.15,0.4 0.15,46 39.82,46 39.82,0.4 ; 11 cut-outs
GND on BOTTOM: 0.15,0.4 0.15,46 39.82,46 39.82,0.4 ; 9 cut-outs
GND on L2: 0.15,0.4 0.15,46 39.82,46 39.82,0.4 ; 1 cut-out
GND on L3: 0.15,0.4 0.15,46 39.82,46 39.82,0.4 ; 2 cut-outs
VDD_EB on TOP: 30.85,12.7 32.85,12.7 33.05,12.5 33.05,11.1 32.85,10.9 30.85,10.9 30.65,11.1 30.65,12.5
VDD_EB on BOTTOM: 31.55,12.7 34.85,12.7 35.1,12.45 35.1,11.05 34.95,10.9 31.55,10.9 31.35,11.1 31.35,12.5
Net_1 on TOP (solid shape): 32.07,51.75 15.67,51.75 15.67,49.95 16.67,49.95 16.67,49.45 17.58,48.13 17.58,46.05 17.12,46.05 17.12,47.98 16.6,48.74 13.47,48.74 13.47,49.95 14.47,49.95 14.47,50.75 8.67,50.75 8.67,48.08 16.67,48.08 16.67,46.05 15.67,46.05 15.67,46.79 14.47,46.79 14.47,46.05 13.47,46.05 13.47,46.79 6.49,46.79 6.49,52.96 32.07,52.96
N314494 on TOP: 17.75,24.2 17.75,23.8 17.4,22.45 17.4,22 17.1,22 17.1,22.45 17.15,23.8 17.15,24.2
N314505 on TOP: 16.25,24.2 16.25,23.8 16.6,22.45 16.6,22 16.9,22 16.9,22.45 16.85,23.7 16.85,24.2

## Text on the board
Ref Des/Silkscreen Bottom: FOR EVALUATION ONLY; | NOT FCC APPROVED FOR RESALE
Ref Des/Silkscreen Top: MODEL: TIDC-CC2650-CC2592-EMK | PCB: REV 1.1.0
XSECTION_CHART: *  SURFACE - AIR 0 MM | L1: TOP CONDUCTOR - COPPER 0.035 MM | *  DIELECTRIC - FR-4 0.175 MM | L2: L2 CONDUCTOR - COPPER 0.018 MM | *  DIELECTRIC - FR-4 1.14 MM | L3: L3 CONDUCTOR - COPPER 0.018 MM | L4: BOTTOM CONDUCTOR - COPPER 0.035 MM | DESIGN CROSS SECTION CHART | ___________________________ | TOTAL THICKNESS 1.596 MM
NCLEGEND-1-4: FIGURE | SIZE | 0.2 | 0.9 | 1.5 | DRILL CHART: TOP to BOTTOM | ALL UNITS ARE IN MILLIMETERS | PLATED | NON-PLATED | QTY | 367 | 34 | 1 | 4
